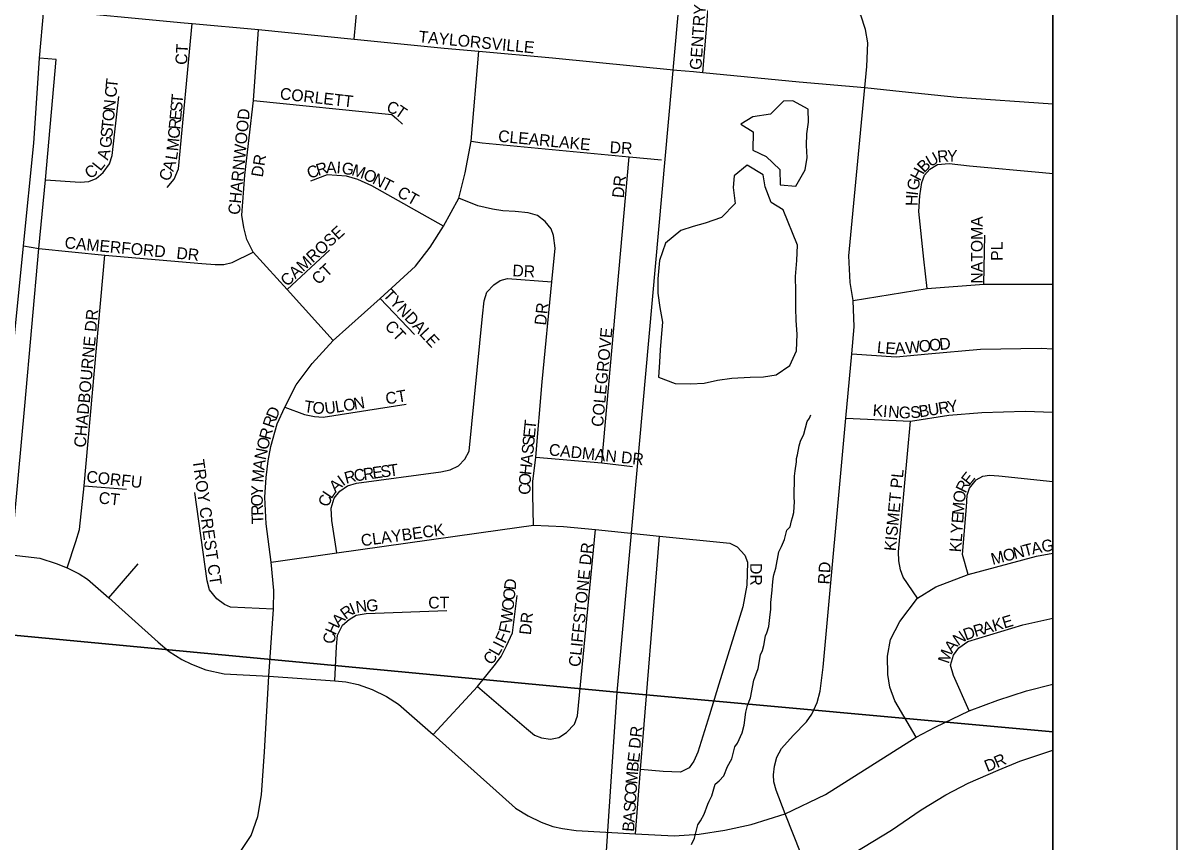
# Model space of a CAD drawing. Extents: x 8.5 to 81.5, y -1.2 to 22.4.
# Drawn here: x 55.423 to 56.353, y 17.008 to 17.667 of the extents above; entities that cross this region are included whole.
import ezdxf

# ---------------------------------------------------------------- set-up
doc = ezdxf.new("R2010")
doc.units = 0
for name, color, linetype in [('GM_X_City_Street', 7, 'Continuous'), ('GM_X_City_Street_Text', 7, 'Continuous'), ('GM_X_Corporation', 7, 'Continuous'), ('GM_X_County', 7, 'Continuous'), ('GM_X_Minor_Lake', 7, 'Continuous'), ('GM_X_Minor_River', 7, 'Continuous'), ('GM_X_Section', 7, 'Continuous'), ('GM_X_State_Route', 7, 'Continuous'), ('SH_Data', 7, 'Continuous')]:
    doc.layers.add(name, color=color, linetype=linetype)

msp = doc.modelspace()

# ---------------------------------------------------------------- linework, layer by layer
at = {"layer": 'GM_X_City_Street'}
for points in [[(56.10152, 17.61496), (56.10152, 17.61502), (56.10296, 17.63197), (56.10378, 17.65112), (56.10195, 17.66171), (56.09808, 17.67333), (56.08901, 17.6882), (56.07709, 17.70103), (56.05163, 17.73017), (56.04572, 17.73934), (56.04185, 17.74769), (56.0394, 17.75523), (56.03798, 17.76154), (56.03655, 17.77483), (56.0506, 17.94359), (56.05281, 17.97457), (56.05444, 17.98151), (56.05993, 17.98872), (56.06647, 17.99218), (56.07359, 17.99276), (56.2436, 17.97852), (56.25272, 17.97869)], [(55.69012, 17.65404), (55.69413, 17.6977), (55.69834, 17.73873), (55.70099, 17.75299), (55.70506, 17.76603), (55.71158, 17.77805), (55.72605, 17.79944), (55.73714, 17.81675), (55.74337, 17.83), (55.74927, 17.84752), (55.752, 17.85863), (55.75371, 17.87422), (55.75532, 17.89451), (55.758, 17.92296), (55.76416, 17.93702), (55.77191, 17.94392), (55.77821, 17.94767), (55.78693, 17.9507), (55.80182, 17.95312), (55.80436, 17.95353)], [(55.97086, 17.62721), (55.9742, 17.66516), (55.97493, 17.67663), (55.97873, 17.68382), (55.98604, 17.68988), (56.00587, 17.70269)], [(55.44021, 17.67791), (55.55321, 17.66724), (55.55979, 17.6666), (55.61318, 17.66171), (55.69012, 17.65404), (55.76252, 17.64684), (55.79043, 17.6444), (55.84992, 17.6389), (55.94996, 17.62891), (55.96331, 17.62782)], [(55.53961, 17.53466), (55.54511, 17.54122), (55.54867, 17.54957), (55.55979, 17.6666)], [(55.67332, 17.41125), (55.6361, 17.45236), (55.61942, 17.47066), (55.60888, 17.48247), (55.60374, 17.49263), (55.60115, 17.50225), (55.59976, 17.51215), (55.60208, 17.54436), (55.60896, 17.60468), (55.61318, 17.66171)], [(55.40643, 17.15813), (55.414, 17.23888), (55.42485, 17.35879), (55.43615, 17.48545), (55.44157, 17.54072), (55.45005, 17.63764), (55.43672, 17.63867)], [(55.6213, 17.14119), (55.62519, 17.19515), (55.62537, 17.21006), (55.62342, 17.23279), (55.61933, 17.26386), (55.61809, 17.28535), (55.61916, 17.30098), (55.62089, 17.31443), (55.62312, 17.32595), (55.62821, 17.3443), (55.63425, 17.35762), (55.64349, 17.37573), (55.65627, 17.39278), (55.67332, 17.41125), (55.71102, 17.44515), (55.73944, 17.47109), (55.75127, 17.48653), (55.76218, 17.50348), (55.77433, 17.52602), (55.77957, 17.54627), (55.78432, 17.57186), (55.79043, 17.6444)], [(55.96331, 17.62782), (55.97086, 17.62721), (56.04857, 17.61974), (56.10152, 17.61502)], [(56.05639, 16.98234), (56.0371, 17.03037), (56.02994, 17.04927), (56.02815, 17.056), (56.02774, 17.06164), (56.02856, 17.06851), (56.03049, 17.07579), (56.0342, 17.0828), (56.04368, 17.09325), (56.0544, 17.10425), (56.05866, 17.11043), (56.06306, 17.11977), (56.0654, 17.12898), (56.06773, 17.14823), (56.08601, 17.34875), (56.09082, 17.4007), (56.09275, 17.42228), (56.09192, 17.44345), (56.08945, 17.45815), (56.08849, 17.47945), (56.10152, 17.61496)], [(56.10152, 17.61502), (56.13143, 17.61192)], [(56.13143, 17.61192), (56.17564, 17.60733), (56.25272, 17.60179)], [(55.44157, 17.54072), (55.46942, 17.53876), (55.47642, 17.53925), (55.48232, 17.54183), (55.48796, 17.54674), (55.49312, 17.5535), (55.49533, 17.56025), (55.50049, 17.6079)], [(55.60896, 17.60468), (55.72046, 17.59323), (55.72438, 17.58978), (55.72909, 17.58555)], [(55.78432, 17.57186), (55.79308, 17.57043), (55.91148, 17.55916), (55.93753, 17.55679)], [(55.88953, 17.31286), (55.91148, 17.55916)], [(56.15166, 17.45329), (56.14881, 17.47692), (56.14494, 17.51523), (56.14555, 17.52786), (56.14738, 17.53865), (56.14942, 17.54456), (56.1537, 17.54925), (56.15981, 17.55312), (56.16918, 17.55394), (56.18569, 17.5521), (56.24436, 17.5466), (56.25272, 17.5458)], [(55.76218, 17.50348), (55.70426, 17.53599), (55.69312, 17.54095), (55.68398, 17.54358), (55.66834, 17.54482), (55.65503, 17.53955)], [(55.8346, 17.26265), (55.83403, 17.28704), (55.83394, 17.29776), (55.83643, 17.31746), (55.84159, 17.37813), (55.84933, 17.45871), (55.85196, 17.48568), (55.85074, 17.49587), (55.8488, 17.50127), (55.84402, 17.50707), (55.8379, 17.51196), (55.83016, 17.51421), (55.81977, 17.51523), (55.80999, 17.51584), (55.80143, 17.51706), (55.78982, 17.51971), (55.77433, 17.52602)], [(56.1973, 17.45675), (56.19812, 17.49627)], [(55.42383, 17.48758), (55.43615, 17.48545), (55.48944, 17.48017), (55.56755, 17.47342), (55.57811, 17.47256), (55.58511, 17.47268), (55.59187, 17.47415), (55.60888, 17.48247)], [(55.4591, 17.22833), (55.46604, 17.24957), (55.4688, 17.25907), (55.47263, 17.29427), (55.48944, 17.48017)], [(55.6361, 17.45236), (55.6703, 17.48421)], [(55.67628, 17.24038), (55.67213, 17.2665), (55.67155, 17.27637), (55.67414, 17.28439), (55.67859, 17.28994), (55.68488, 17.29426), (55.69192, 17.29636), (55.75993, 17.3055), (55.76745, 17.30735), (55.77424, 17.31043), (55.77918, 17.31586), (55.78263, 17.32228), (55.79337, 17.43101), (55.79473, 17.44323), (55.79707, 17.45027), (55.8025, 17.45631), (55.80768, 17.45964), (55.81349, 17.46137), (55.84933, 17.45871)], [(56.09192, 17.44345), (56.15166, 17.45329), (56.1973, 17.45675), (56.25272, 17.45675)], [(55.71102, 17.44515), (55.73861, 17.41612)], [(56.09082, 17.4007), (56.12657, 17.39808), (56.15238, 17.4006), (56.19442, 17.40439), (56.24333, 17.40529), (56.25272, 17.40467)], [(55.63425, 17.35762), (55.65003, 17.35175), (55.65809, 17.3501), (55.66525, 17.34973), (55.732, 17.36019)], [(56.08601, 17.34875), (56.1381, 17.34654), (56.16916, 17.35125), (56.19569, 17.35352), (56.23041, 17.35439), (56.25272, 17.35356)], [(56.14371, 17.2039), (56.13234, 17.22072), (56.13007, 17.22683), (56.12885, 17.2339), (56.12842, 17.24114), (56.1381, 17.34654)], [(55.83643, 17.31746), (55.88953, 17.31286), (55.91424, 17.30991)], [(56.18467, 17.22303), (56.18015, 17.23913), (56.18322, 17.27748), (56.18373, 17.28694), (56.18564, 17.29244), (56.19114, 17.29908), (56.19651, 17.30215), (56.20189, 17.30292), (56.20917, 17.30241), (56.25272, 17.29795)], [(55.47263, 17.29427), (55.50677, 17.29167)], [(55.62519, 17.19515), (55.59043, 17.19674), (55.58568, 17.19886), (55.57952, 17.20325), (55.5737, 17.21048), (55.57176, 17.21788), (55.56172, 17.28904)], [(55.62342, 17.23279), (55.67628, 17.24038), (55.80758, 17.25904), (55.8346, 17.26265), (55.85883, 17.26166), (55.88437, 17.2592), (55.9361, 17.2538), (55.99275, 17.24807), (55.99848, 17.24529), (56.00486, 17.23858), (56.00699, 17.23301), (56.00634, 17.21435), (56.00322, 17.19683), (55.9839, 17.13462), (55.97621, 17.11006), (55.96688, 17.07978), (55.9636, 17.07274), (55.95984, 17.06717), (55.95297, 17.06389), (55.93905, 17.06422), (55.92071, 17.06586)], [(55.78958, 17.13282), (55.82903, 17.09893), (55.83525, 17.09353), (55.84098, 17.0914), (55.84818, 17.09041), (55.8549, 17.09173), (55.86112, 17.09565), (55.86761, 17.10234), (55.86996, 17.10908), (55.88437, 17.2592)], [(55.91679, 17.01416), (55.92071, 17.06586), (55.9361, 17.2538)], [(55.414, 17.23888), (55.43709, 17.23613), (55.45023, 17.23184), (55.4591, 17.22833), (55.46858, 17.22359), (55.47546, 17.21931), (55.49258, 17.20417), (55.53217, 17.1684), (55.54104, 17.16106), (55.55143, 17.15449), (55.55923, 17.15067), (55.57069, 17.14624), (55.58537, 17.14303), (55.6213, 17.14119), (55.67465, 17.13737), (55.68336, 17.13645), (55.69345, 17.13447), (55.70476, 17.13049), (55.71622, 17.12484), (55.72571, 17.11857), (55.75373, 17.09412), (55.80948, 17.04427), (55.82002, 17.03495), (55.83027, 17.02868), (55.84081, 17.02348), (55.85014, 17.02012), (55.85778, 17.01844), (55.86879, 17.01691), (55.91679, 17.01416), (55.94783, 17.01263), (55.968, 17.014), (55.98864, 17.01706), (56.00989, 17.02165), (56.0371, 17.03037), (56.06966, 17.0458), (56.14273, 17.09197), (56.15802, 17.10007), (56.18538, 17.11306), (56.20862, 17.12178), (56.23171, 17.12927), (56.25272, 17.13472)], [(56.14273, 17.09197), (56.12567, 17.12125), (56.12152, 17.13226), (56.11989, 17.14255), (56.11953, 17.15716), (56.12206, 17.17052), (56.12964, 17.18514), (56.14371, 17.2039), (56.15851, 17.21292), (56.18467, 17.22303), (56.23954, 17.23765), (56.25272, 17.24012)], [(55.49258, 17.20417), (55.51627, 17.23154)], [(55.75373, 17.09412), (55.78958, 17.13282), (55.80398, 17.15066), (55.80857, 17.15705), (55.8128, 17.16565), (55.81774, 17.17587), (55.82133, 17.20616)], [(55.67465, 17.13737), (55.67579, 17.16507), (55.67676, 17.17407), (55.68071, 17.18226), (55.68611, 17.18668), (55.69167, 17.19012), (55.6997, 17.19142), (55.76485, 17.19388)], [(56.18538, 17.11306), (56.17288, 17.14168), (56.17043, 17.15008), (56.17268, 17.15799), (56.17698, 17.16395), (56.1843, 17.16903), (56.22855, 17.18251), (56.25272, 17.18778)], [(55.38314, 16.96798), (55.52151, 16.95878), (55.53491, 16.96023), (55.54523, 16.96229), (55.56235, 16.96827), (55.57927, 16.979), (55.59432, 16.99344), (55.60712, 17.01283), (55.61248, 17.0281), (55.61557, 17.04543), (55.61805, 17.08029), (55.6213, 17.14119)], [(55.97072, 16.96168), (56.00806, 16.96739), (56.01448, 16.96871), (56.05639, 16.98234), (56.08516, 16.99442), (56.1228, 17.01706), (56.14666, 17.03348), (56.16665, 17.04562), (56.18471, 17.055), (56.20877, 17.0655), (56.22632, 17.07264), (56.25272, 17.08155)]]:
    msp.add_lwpolyline(points, dxfattribs=at)
at = {"layer": 'GM_X_Corporation'}
msp.add_line((56.25272, 15.06706), (56.25272, 20.11042), dxfattribs=at)
at = {"layer": 'GM_X_County'}
msp.add_lwpolyline([(54.08792, 21.25055), (49.45272, 21.25055), (49.45272, 14.45055), (56.25272, 14.45055), (56.25272, 19.11082)], dxfattribs=at)
at = {"layer": 'GM_X_Minor_Lake'}
for points in [[(56.04339, 17.60419), (56.03578, 17.60396), (56.02532, 17.59353), (56.01123, 17.59154), (56.00162, 17.58566), (56.01137, 17.57938), (56.01108, 17.56457)], [(56.01108, 17.56457), (56.02199, 17.55941), (56.0328, 17.54893), (56.03332, 17.53677), (56.04584, 17.53575), (56.05332, 17.5489), (56.05503, 17.55874), (56.05446, 17.56825), (56.05464, 17.57774), (56.05597, 17.58722), (56.05579, 17.59748), (56.04339, 17.60419)], [(56.04719, 17.48824), (56.03559, 17.51658), (56.02583, 17.52248), (56.02114, 17.53511), (56.01942, 17.54464), (56.00666, 17.5525), (55.99624, 17.54397), (55.99529, 17.53449), (55.99694, 17.52154), (55.98608, 17.51037), (55.97269, 17.5057), (55.96315, 17.50323), (55.95321, 17.50002), (55.94085, 17.48963), (55.93602, 17.47567), (55.93459, 17.46088), (55.93474, 17.44948), (55.93642, 17.43805), (55.93846, 17.42623), (55.93746, 17.41371), (55.9365, 17.40385), (55.93593, 17.39399), (55.93531, 17.38184), (55.94851, 17.37664), (55.96104, 17.37638), (55.97206, 17.37692)], [(55.97206, 17.37692), (55.98275, 17.37936), (55.99418, 17.38103), (56.00901, 17.38187), (56.01965, 17.38203), (56.02994, 17.38373), (56.0411, 17.3911), (56.04627, 17.40315), (56.04692, 17.41643), (56.04599, 17.42747), (56.04581, 17.43773), (56.0457, 17.45103), (56.04555, 17.46281), (56.04656, 17.47571), (56.04719, 17.48824)]]:
    msp.add_lwpolyline(points, dxfattribs=at)
at = {"layer": 'GM_X_Minor_River'}
msp.add_lwpolyline([(55.96175, 17.00551), (55.96413, 17.01079), (55.96701, 17.02137), (55.96897, 17.02475), (55.97212, 17.03001), (55.97494, 17.03794), (55.97613, 17.04057), (55.97811, 17.04471), (55.98096, 17.05416), (55.98405, 17.05676), (55.98793, 17.06086), (55.99074, 17.06841), (55.99428, 17.07442), (55.99676, 17.08425), (55.99871, 17.08725), (56.00268, 17.09553), (56.00432, 17.10158), (56.00568, 17.1122), (56.00692, 17.11749), (56.00933, 17.12353), (56.0119, 17.13792), (56.0135, 17.14207), (56.01551, 17.14735), (56.01725, 17.15834), (56.01884, 17.16172), (56.02006, 17.16588), (56.02135, 17.17346), (56.02255, 17.17609), (56.02417, 17.181), (56.02513, 17.19086), (56.02558, 17.19465), (56.0257, 17.20035), (56.02666, 17.21022), (56.02712, 17.21401), (56.02762, 17.2197), (56.02806, 17.22273), (56.02968, 17.22802), (56.03223, 17.24127), (56.03422, 17.24541), (56.03661, 17.25106), (56.03866, 17.25863), (56.04137, 17.26123), (56.04223, 17.26616), (56.04304, 17.2688), (56.04427, 17.27296), (56.04483, 17.28169), (56.04451, 17.28473), (56.04487, 17.30221), (56.04533, 17.30638), (56.04624, 17.31358), (56.04629, 17.31624), (56.04712, 17.31927), (56.0484, 17.32646), (56.04962, 17.33024), (56.05239, 17.33588), (56.05488, 17.3461), (56.05683, 17.34872), (56.05794, 17.35151)], dxfattribs=at)
at = {"layer": 'GM_X_Section'}
for p, q in [((56.25272, 17.09637), (56.25272, 18.10802)), ((56.25272, 16.08816), (56.25272, 17.09637))]:
    msp.add_line(p, q, dxfattribs=at)
for points in [[(54.98609, 18.22332), (55.99217, 18.13287), (55.90174, 17.12832), (54.89877, 17.22287)], [(54.89877, 17.22287), (55.90174, 17.12832), (55.83452, 16.12902), (54.83971, 16.19386)]]:
    msp.add_lwpolyline(points, close=True, dxfattribs=at)
for points in [[(56.25272, 18.10802), (55.99217, 18.13287), (55.90174, 17.12832), (56.25272, 17.09637)], [(56.25272, 17.09637), (55.90174, 17.12832), (55.83452, 16.12902), (56.25272, 16.08816)]]:
    msp.add_lwpolyline(points, dxfattribs=at)
at = {"layer": 'GM_X_State_Route'}
msp.add_lwpolyline([(55.32231, 16.03925), (55.33053, 16.15929), (55.33703, 16.25621), (55.34744, 16.41921), (55.35534, 16.54214), (55.36319, 16.66602), (55.37059, 16.76959), (55.37522, 16.8474), (55.38314, 16.96798), (55.38784, 17.06714), (55.396, 17.19205), (55.4007, 17.23979), (55.41275, 17.37034), (55.41563, 17.40422), (55.42383, 17.48758), (55.43205, 17.57033), (55.43672, 17.63867), (55.44021, 17.67791), (55.44836, 17.76072), (55.45699, 17.85529), (55.45757, 17.86126)], dxfattribs=at)
at = {"layer": 'SH_Data'}
for p, q in [((56.35272, 21.35055), (56.35272, 14.35055)), ((56.25272, 21.25055), (56.25272, 14.45055))]:
    msp.add_line(p, q, dxfattribs=at)

# ---------------------------------------------------------------- texts
at = {"layer": 'GM_X_City_Street_Text'}
for s, height, rotation, p in [('GENTRY', 0.00947, 85.91271, (55.96967, 17.62896)), ('TAYLORSVILLE', 0.0094697, 354.50936, (55.74164, 17.65144)), ('CT', 0.00947, 86.82218, (55.5555, 17.6331)), ('T', 0.00947, 84.23686, (55.49925, 17.61408)), ('C', 0.00947, 84.20965, (55.49849, 17.60661)), ('T', 0.00947, 84.66791, (55.552, 17.60167)), ('CORLETT', 0.00947, 353.55846, (55.62998, 17.60561)), ('N', 0.00947, 84.22533, (55.4974, 17.59583)), ('S', 0.00947, 84.66791, (55.55138, 17.59503)), ('C', 0.00947, 341.6956, (55.71553, 17.59569)), ('T', 0.00947, 325.52947, (55.72202, 17.59364)), ('O', 0.00947, 84.2198, (55.49656, 17.58754)), ('E', 0.00947, 84.66791, (55.55076, 17.58839)), ('CHARNWOOD', 0.00947, 84.47433, (55.598, 17.51225)), ('S', 0.00947, 84.22688, (55.49522, 17.57428)), ('T', 0.00947, 84.23686, (55.49589, 17.58091)), ('C', 0.00947, 84.66791, (55.54937, 17.57346)), ('R', 0.00947, 84.66791, (55.55007, 17.58093)), ('G', 0.00947, 84.49641, (55.49442, 17.56599)), ('M', 0.00947, 84.66791, (55.54844, 17.5635)), ('CLEARLAKE', 0.00947, 354.49493, (55.80578, 17.57144)), ('A', 0.00947, 73.84551, (55.49174, 17.5561)), ('L', 0.00947, 80.66385, (55.54727, 17.55621)), ('DR', 0.00947, 356.98902, (55.89571, 17.56228)), ('U', 0.00947, 29.3518, (56.15393, 17.5508)), ('R', 0.00947, 6.10688, (56.16023, 17.55458)), ('Y', 0.00947, 358.90712, (56.16738, 17.55536)), ('L', 0.00947, 51.26513, (55.4857, 17.54731)), ('A', 0.00947, 72.65572, (55.54446, 17.54685)), ('DR', 0.00947, 81.02146, (55.61644, 17.54243)), ('R', 0.00947, 16.7225, (55.66104, 17.54386)), ('A', 0.00947, 0.93991, (55.66754, 17.54591)), ('I', 0.00947, 355.75553, (55.67565, 17.54605)), ('G', 0.00947, 351.61948, (55.67962, 17.54576)), ('M', 0.00947, 341.52474, (55.68744, 17.54465)), ('B', 0.00947, 44.82825, (56.14915, 17.54592)), ('C', 0.00947, 32.99638, (55.47697, 17.54102)), ('C', 0.00947, 64.6476, (55.54072, 17.53873)), ('C', 0.00947, 20.07854, (55.65413, 17.54133)), ('O', 0.00947, 335.26302, (55.69667, 17.54158)), ('N', 0.00947, 332.92662, (55.70415, 17.53814)), ('H', 0.00947, 62.03681, (56.14569, 17.53916)), ('T', 0.00947, 332.42086, (55.71155, 17.53436)), ('CT', 0.00947, 330.64938, (55.72399, 17.52789)), ('DR', 0.00947, 83.982, (55.90717, 17.52569)), ('G', 0.00947, 79.62869, (56.14444, 17.53169)), ('H', 0.00947, 88.88525, (56.14382, 17.51962)), ('I', 0.00947, 83.20585, (56.14397, 17.5277)), ('NATOMA', 0.00947, 90, (56.19633, 17.45717)), ('CAMROSE', 0.00947, 42.56473, (55.63607, 17.45431)), ('CAMERFORD', 0.00947, 354.68452, (55.45664, 17.48561)), ('PL', 0.00947, 90, (56.21244, 17.4755)), ('DR', 0.00947, 353.99339, (55.54663, 17.47727)), ('CT', 0.00947, 42.7017, (55.66128, 17.45567)), ('DR', 0.00947, 356.98842, (55.81737, 17.46311)), ('TYNDALE', 0.00947, 313.15345, (55.71274, 17.44755)), ('CHADBOURNE DR', 0.0094697, 84.71797, (55.47383, 17.32483)), ('DR', 0.00947, 83.99458, (55.84468, 17.42319)), ('CT', 0.00947, 312.87172, (55.71415, 17.4223)), ('COLEGROVE', 0.00947, 84.49231, (55.8905, 17.3415)), ('L', 0.00947, 354.2269, (56.11081, 17.40144)), ('E', 0.00947, 355.03729, (56.11759, 17.40075)), ('A', 0.00947, 3.15054, (56.12569, 17.40016)), ('W', 0.00947, 6.11098, (56.13454, 17.40066)), ('O', 0.00947, 6.12936, (56.14532, 17.40181)), ('O', 0.00947, 6.13258, (56.15361, 17.4027)), ('D', 0.00947, 6.10852, (56.16189, 17.40359)), ('CT', 0.00947, 9.45641, (55.71615, 17.35976)), ('T', 0.00947, 351.80422, (55.64922, 17.35393)), ('O', 0.00947, 353.52602, (55.65613, 17.35294)), ('U', 0.00947, 7.25651, (55.66688, 17.35202)), ('L', 0.00947, 9.51876, (55.67556, 17.35313)), ('O', 0.00947, 9.46232, (55.68213, 17.35423)), ('N', 0.00947, 9.46232, (55.69035, 17.3556)), ('K', 0.00947, 355.49232, (56.10743, 17.35061)), ('I', 0.00947, 355.49404, (56.11574, 17.34996)), ('N', 0.00947, 355.47053, (56.11989, 17.34963)), ('G', 0.00947, 356.8065, (56.12844, 17.34896)), ('S', 0.00947, 6.60941, (56.13852, 17.34855)), ('B', 0.00947, 9.21995, (56.14561, 17.34938)), ('U', 0.00947, 9.27048, (56.15302, 17.35058)), ('R', 0.00947, 9.26673, (56.16125, 17.35192)), ('Y', 0.00947, 9.26468, (56.16865, 17.35313)), ('R', 0.00947, 71.18103, (55.62509, 17.34031)), ('D', 0.00947, 67.05396, (55.62745, 17.34724)), ('R', 0.00947, 74.89182, (55.62252, 17.33081)), ('E', 0.00947, 84.28611, (55.83561, 17.3326)), ('T', 0.00947, 84.28124, (55.83628, 17.33923)), ('O', 0.00947, 76.27646, (55.62055, 17.32277)), ('S', 0.00947, 84.28124, (55.83495, 17.32596)), ('N', 0.00947, 78.4457, (55.61891, 17.3147)), ('S', 0.00947, 84.28124, (55.83429, 17.31932)), ('CADMAN DR', 0.00947, 353.95277, (55.84659, 17.31895)), ('TROY CREST CT', 0.0094697, 278.12982, (55.55988, 17.31492)), ('A', 0.00947, 82.4169, (55.61783, 17.30661)), ('T', 0.00947, 7.9485, (55.71861, 17.30182)), ('H', 0.00947, 84.39596, (55.83264, 17.30274)), ('A', 0.00947, 84.28505, (55.83346, 17.31103)), ('CORFU', 0.00947, 353.79543, (55.47414, 17.29728)), ('M', 0.00947, 84.89297, (55.61696, 17.29676)), ('I', 0.00947, 35.96953, (55.68107, 17.29382)), ('R', 0.00947, 14.68422, (55.68361, 17.29587)), ('C', 0.00947, 9.17085, (55.69062, 17.29773)), ('R', 0.00947, 8.11293, (55.69798, 17.29891)), ('E', 0.00947, 7.97556, (55.7054, 17.29997)), ('S', 0.00947, 7.97556, (55.712, 17.3009)), ('O', 0.00947, 86.76318, (55.83218, 17.29453)), ('KISMET PL', 0.00947, 84.44694, (56.12634, 17.24151)), ('E', 0.00947, 51.71999, (56.18557, 17.29413)), ('Y', 0.00947, 87.72598, (55.61647, 17.28606)), ('A', 0.00947, 42.4648, (55.67514, 17.28837)), ('C', 0.00947, 89.82997, (55.83216, 17.28716)), ('R', 0.00947, 63.30463, (56.18247, 17.28786)), ('CT', 0.00947, 353.66381, (55.48401, 17.28025)), ('O', 0.00947, 91.11475, (55.61664, 17.27788)), ('C', 0.00947, 71.18103, (55.66971, 17.27676)), ('L', 0.00947, 56.39326, (55.67184, 17.28328)), ('O', 0.00947, 83.60429, (56.18179, 17.28042)), ('R', 0.00947, 92.14294, (55.61692, 17.27043)), ('M', 0.00947, 85.73399, (56.18106, 17.27054)), ('T', 0.00947, 92.13122, (55.61716, 17.26376)), ('E', 0.00947, 85.75954, (56.18056, 17.2639)), ('CLAYBECK', 0.00947, 7.69793, (55.69621, 17.2456)), ('Y', 0.00947, 85.73373, (56.17994, 17.25558)), ('CLIFFSTONE DR', 0.0094697, 84.01851, (55.87217, 17.14819)), ('K', 0.00947, 85.73373, (56.17883, 17.24062)), ('L', 0.00947, 85.75954, (56.17945, 17.24894)), ('T', 0.00947, 14.5795, (56.23011, 17.2373)), ('A', 0.00947, 12.15428, (56.23646, 17.23896)), ('G', 0.00947, 10.64114, (56.24455, 17.2407)), ('M', 0.00947, 14.65919, (56.20432, 17.23056)), ('O', 0.00947, 14.65122, (56.214, 17.23309)), ('N', 0.00947, 14.62443, (56.22205, 17.2352)), ('DR', 0.00947, 270, (56.00906, 17.23217)), ('RD', 0.00947, 86.82218, (56.073, 17.21477)), ('D', 0.00947, 83.78499, (55.82009, 17.21005)), ('O', 0.00947, 83.75876, (55.81918, 17.20177)), ('I', 0.00947, 23.47416, (55.68886, 17.19047)), ('N', 0.00947, 8.093, (55.69204, 17.19195)), ('G', 0.00947, 3.43319, (55.70009, 17.1931)), ('CT', 0.00947, 0.00001, (55.74978, 17.19562)), ('O', 0.00947, 83.78499, (55.81828, 17.19348)), ('R', 0.00947, 36.15592, (55.68329, 17.18632)), ('W', 0.00947, 83.76912, (55.8171, 17.18271)), ('DR', 0.00947, 83.99458, (55.83237, 17.174)), ('H', 0.00947, 65.3607, (55.67495, 17.17361)), ('A', 0.00947, 47.17943, (55.67798, 17.18053)), ('F', 0.00947, 77.28433, (55.81544, 17.17505)), ('R', 0.00947, 16.54575, (56.19039, 17.17253)), ('A', 0.00947, 16.37474, (56.19757, 17.17467)), ('K', 0.00947, 16.39066, (56.20557, 17.17702)), ('E', 0.00947, 16.39571, (56.21356, 17.17937)), ('C', 0.00947, 86.08739, (55.67466, 17.167)), ('F', 0.00947, 64.27332, (55.81178, 17.16684)), ('N', 0.00947, 35.12095, (56.17647, 17.16524)), ('D', 0.00947, 20.03165, (56.1827, 17.16973)), ('L', 0.00947, 60.33865, (55.80625, 17.15671)), ('I', 0.00947, 62.90952, (55.80977, 17.1629)), ('A', 0.00947, 50.10766, (56.1716, 17.15929)), ('C', 0.00947, 49.83065, (55.80033, 17.14942)), ('M', 0.00947, 71.21368, (56.16883, 17.15062)), ('DR', 0.00947, 83.99458, (55.92051, 17.08235)), ('E', 0.00947, 82.90547, (55.91953, 17.07116)), ('B', 0.00947, 83.98972, (55.91875, 17.06375)), ('D', 0.00947, 22.09363, (56.19996, 17.06383)), ('R', 0.00947, 23.5383, (56.20792, 17.06706)), ('M', 0.00947, 86.00781, (55.91806, 17.05386)), ('O', 0.00947, 86.17566, (55.9175, 17.04556)), ('C', 0.00947, 86.16007, (55.917, 17.03807)), ('S', 0.00947, 86.17137, (55.91656, 17.03142)), ('B', 0.00947, 86.1843, (55.9155, 17.01562)), ('A', 0.00947, 86.17284, (55.916, 17.02311))]:
    msp.add_text(s, height=height, rotation=rotation, dxfattribs=at).set_placement(p)

doc.saveas('drawing.dxf')
